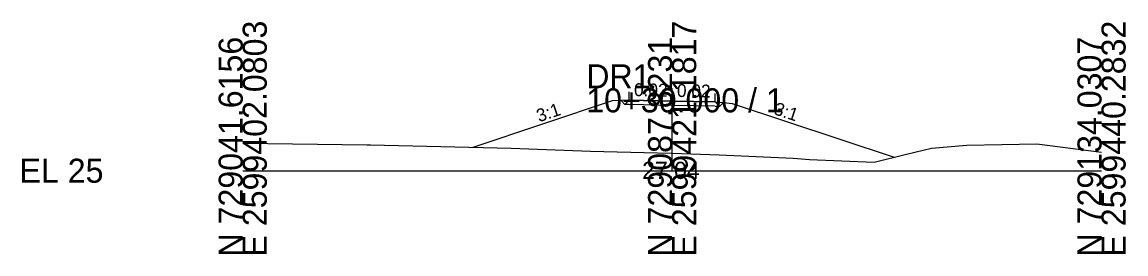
# Model space of a CAD drawing. Extents: x -26 to 1162, y -10 to 9515.
# Drawn here: x -25.7 to 102.8, y 1490.3 to 1517.3 of the extents above; entities that cross this region are included whole.
import ezdxf

# ---------------------------------------------------------------- set-up
doc = ezdxf.new("R2010")
doc.units = 0
for name, color, linetype in [('Exist Cross Section Cell', 7, 'Continuous'), ('Exist XS Center Line Elevation Label', 7, 'Continuous'), ('Exist XS Ground Line', 7, 'Continuous'), ('Prop XS Ditch Slope Text', 7, 'Continuous'), ('Prop XS Dump Level', 7, 'Continuous'), ('Prop XS EOT Tick Mark', 7, 'Continuous'), ('Prop XS Finish Grade', 7, 'Continuous'), ('Prop XS Finish Grade Earthwork', 7, 'Continuous'), ('Prop XS Finish Grade Pavement', 7, 'Continuous'), ('Prop XS Pvmt Edge Slope', 7, 'Continuous'), ('Prop XS SE Text', 7, 'Continuous'), ('Prop XS Subgrade Earthwork', 7, 'Continuous')]:
    doc.layers.add(name, color=color, linetype=linetype)

msp = doc.modelspace()

# ---------------------------------------------------------------- linework, layer by layer
at = {"layer": 'Exist Cross Section Cell'}
for p, q in [((50, 1500), (50, 1509.6)), ((0, 1500), (50, 1500)), ((50, 1500), (100, 1500))]:
    msp.add_line(p, q, dxfattribs=at)
at = {"layer": 'Exist XS Ground Line'}
msp.add_lwpolyline([(0, 1503.2), (14.5, 1503.01), (14.86, 1503), (31.26, 1502.62), (40.49, 1502.27), (48.3, 1502.1), (50, 1502.04), (55.49, 1501.85), (64.11, 1501.47), (64.61, 1501.44), (66, 1501.29), (73.53, 1500.99), (77.29, 1501.93), (80.2, 1502.61), (84.3, 1502.98), (92.47, 1503.15), (100, 1502.17)], dxfattribs=at)
at = {"layer": 'Prop XS Dump Level'}
for p, q in [((50, 1508.11), (45, 1508.21)), ((45, 1508.21), (50, 1508.11)), ((55, 1508.01), (50, 1508.11)), ((50, 1508.11), (55, 1508.01))]:
    msp.add_line(p, q, dxfattribs=at)
at = {"layer": 'Prop XS EOT Tick Mark'}
for p, q in [((45, 1508.21), (45, 1509.21)), ((55, 1508.01), (55, 1509.01))]:
    msp.add_line(p, q, dxfattribs=at)
at = {"layer": 'Prop XS Finish Grade'}
for p, q in [((45, 1508.21), (44.06, 1508.17)), ((55, 1508.01), (55.98, 1507.93))]:
    msp.add_line(p, q, dxfattribs=at)
at = {"layer": 'Prop XS Finish Grade Earthwork'}
for p, q in [((43, 1508.13), (26.78, 1502.72)), ((44.06, 1508.17), (43, 1508.13)), ((55.98, 1507.93), (57, 1507.85)), ((57, 1507.85), (75.85, 1501.57))]:
    msp.add_line(p, q, dxfattribs=at)
at = {"layer": 'Prop XS Finish Grade Pavement'}
for p, q in [((45, 1508.21), (50, 1508.11)), ((50, 1508.11), (55, 1508.01))]:
    msp.add_line(p, q, dxfattribs=at)
at = {"layer": 'Prop XS Pvmt Edge Slope'}
for p, q in [((44.06, 1508.17), (44.51, 1507.72)), ((45, 1508.21), (44.51, 1507.72)), ((55, 1508.01), (55.51, 1507.5)), ((55.98, 1507.93), (55.51, 1507.5))]:
    msp.add_line(p, q, dxfattribs=at)
at = {"layer": 'Prop XS Subgrade Earthwork'}
for p, q in [((44.51, 1507.72), (44.06, 1508.17)), ((44.51, 1507.72), (44.06, 1508.17)), ((45, 1507.71), (44.51, 1507.72)), ((50, 1507.61), (45, 1507.71)), ((55.51, 1507.5), (55.98, 1507.93)), ((55.51, 1507.5), (55.98, 1507.93)), ((55, 1507.51), (50, 1507.61)), ((55, 1507.51), (55.51, 1507.5))]:
    msp.add_line(p, q, dxfattribs=at)

# ---------------------------------------------------------------- texts
at = {"layer": 'Exist Cross Section Cell'}
for s, p in [('E 2599402.0803', (2.8, 1490)), ('E 2599421.1817', (52.8, 1490)), ('E 2599440.2832', (102.8, 1490)), ('N 729041.6156', (0, 1490)), ('N 729087.8231', (50, 1490)), ('N 729134.0307', (100, 1490))]:
    msp.add_text(s, height=2.8, rotation=90, dxfattribs=at).set_placement(p)
for s, p in [('DR1', (40, 1509.6)), ('10+30.000 / 1', (40, 1506.8)), ('EL 25', (-26, 1498.6))]:
    msp.add_text(s, height=2.8, dxfattribs=at).set_placement(p)
at = {"layer": 'Exist XS Center Line Elevation Label'}
msp.add_text('27.04', height=2, dxfattribs=at).set_placement((46.51, 1499.04))
at = {"layer": 'Prop XS Ditch Slope Text'}
for rotation, p in [(18.4349, (34.5, 1505.64)), (341.5883, (61.74, 1506.61))]:
    msp.add_text('3:1', height=1.5, rotation=rotation, dxfattribs=at).set_placement(p)
at = {"layer": 'Prop XS Dump Level'}
for p in [(43, 1508.09), (57, 1507.81)]:
    msp.add_text('Case1', height=0.04, dxfattribs=at).set_placement(p)
at = {"layer": 'Prop XS SE Text'}
for p in [(45.55, 1508.7), (50.55, 1508.6)]:
    msp.add_text('0.02', height=1.5, rotation=358.8542, dxfattribs=at).set_placement(p)

doc.saveas('drawing.dxf')
